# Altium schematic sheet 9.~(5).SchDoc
size 420 x 297 mm
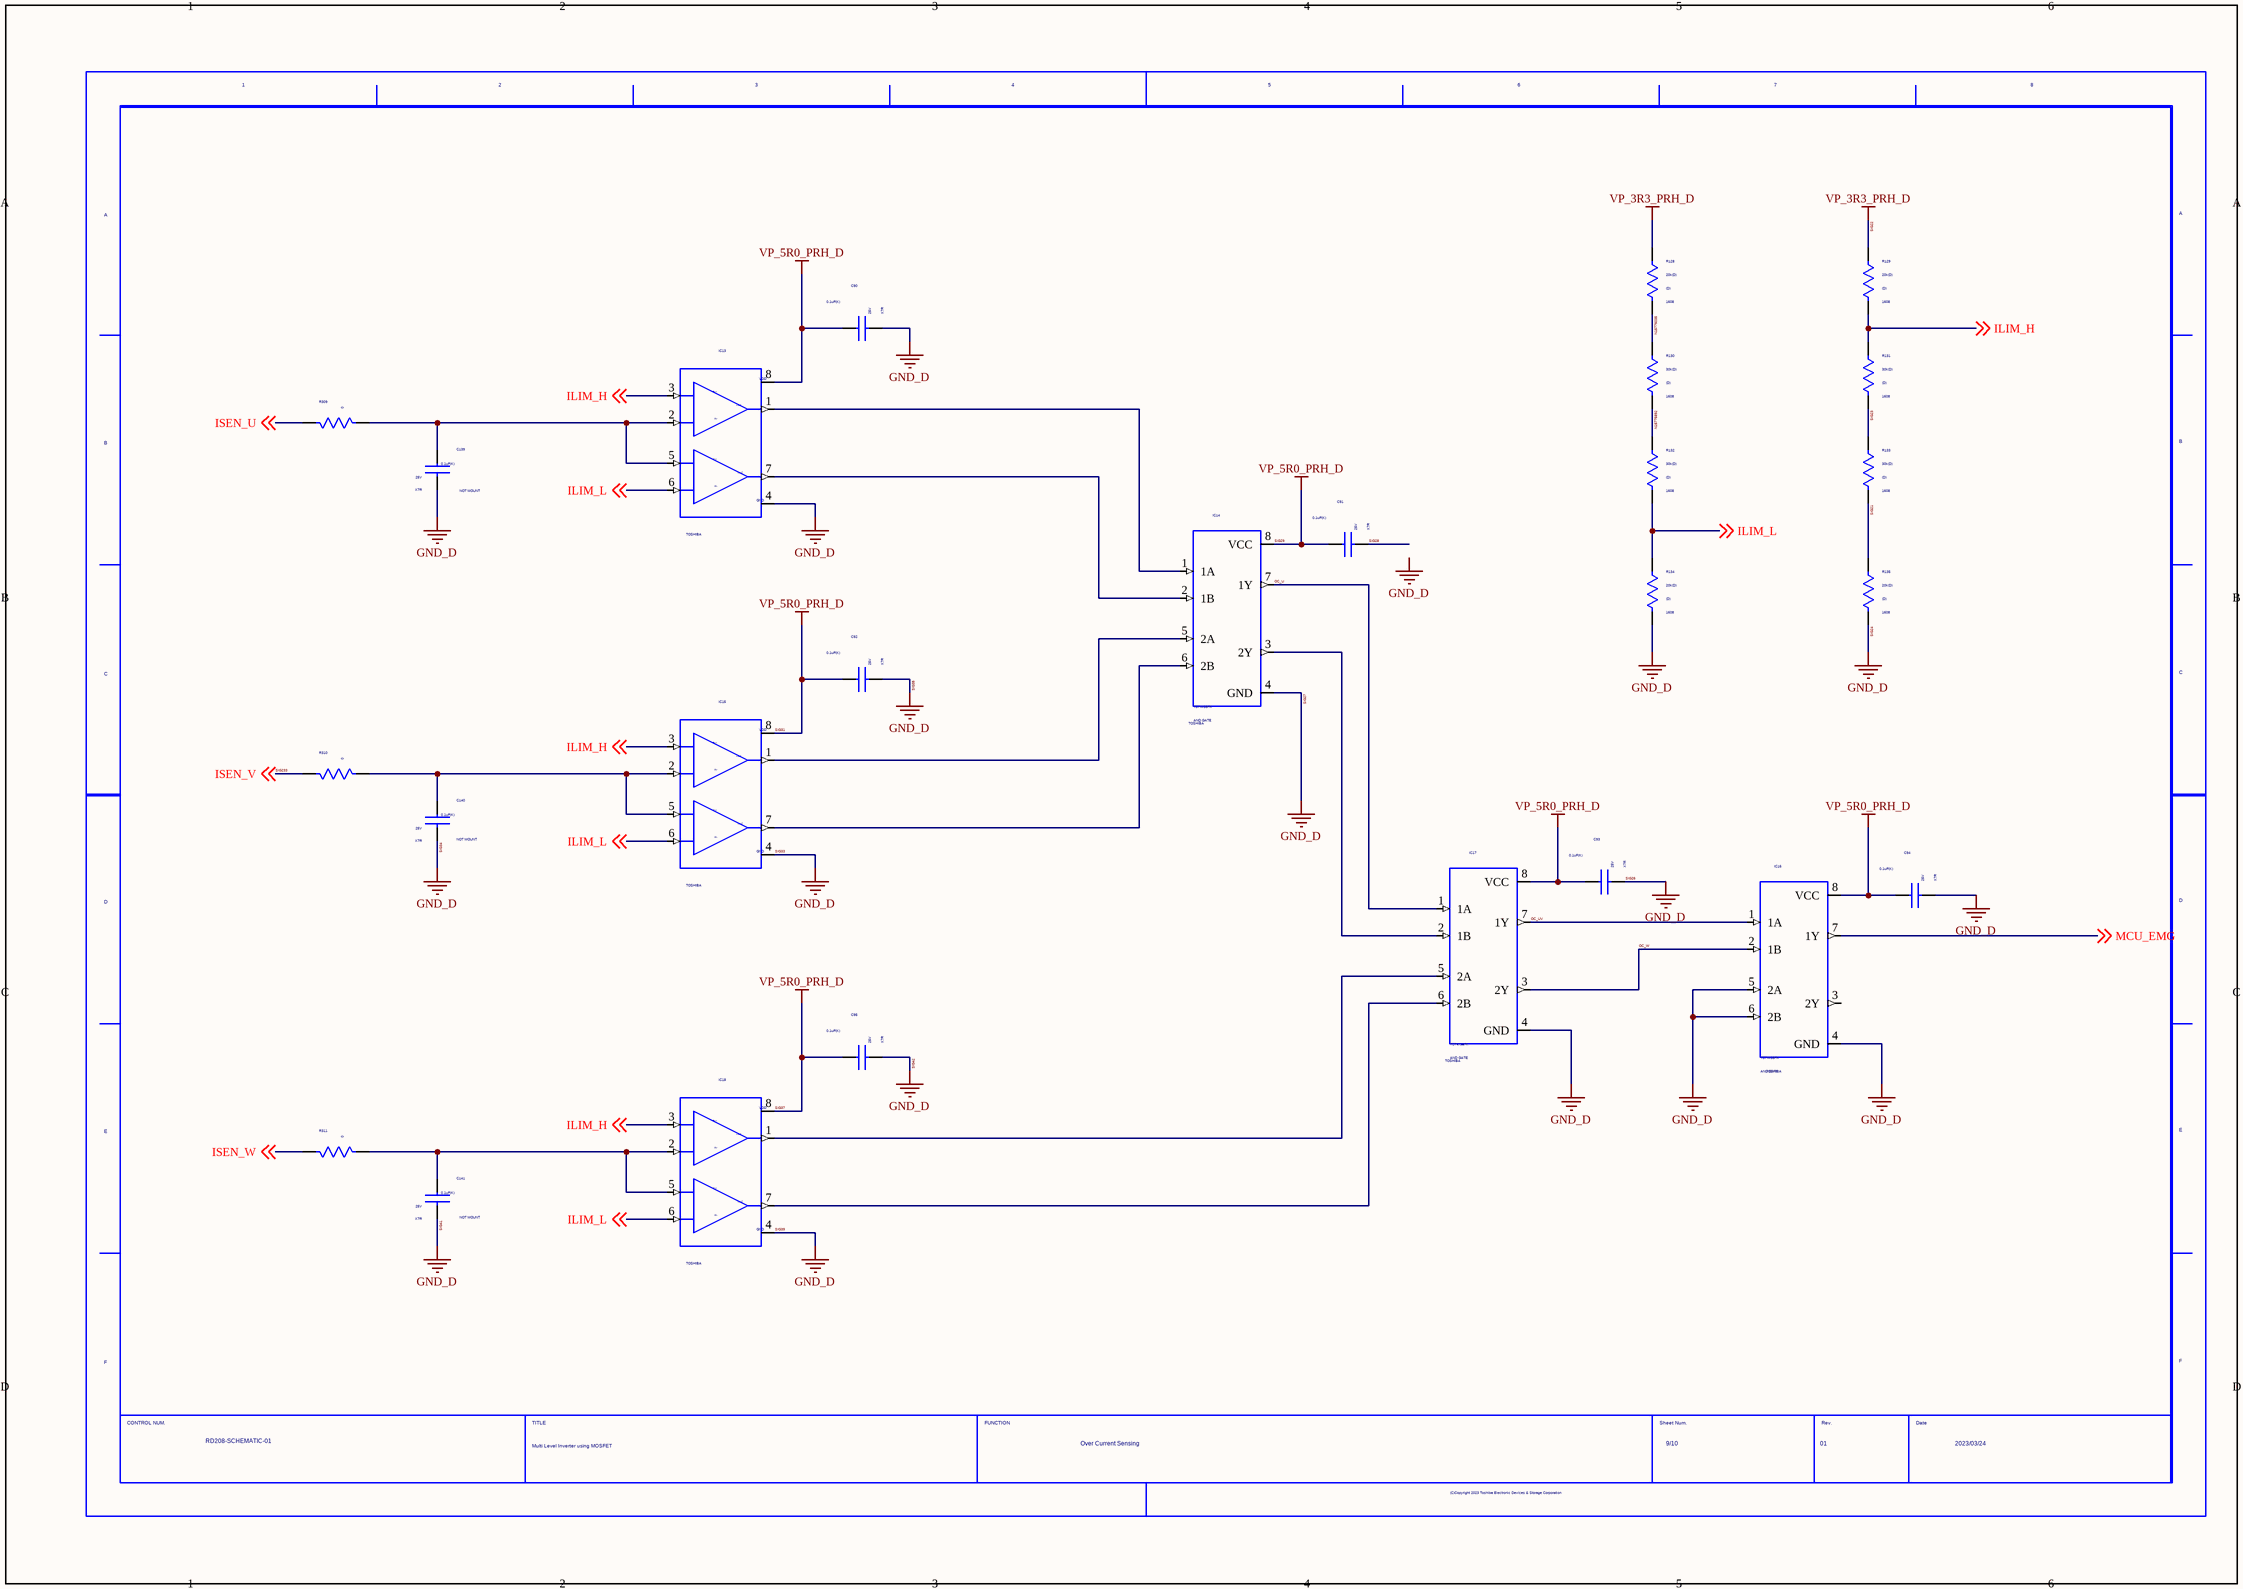
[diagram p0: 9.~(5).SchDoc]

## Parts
C90  VAL2: 25V  VALUE4: X7R  VAL1: 0.1uF(K)  (hidden comment: GRM155R71E104KE14D)
C91  VAL2: 25V  VALUE4: X7R  VAL1: 0.1uF(K)  (hidden comment: GRM155R71E104KE14D)
C92  VAL2: 25V  VALUE4: X7R  VAL1: 0.1uF(K)  (hidden comment: GRM155R71E104KE14D)
C93  VAL2: 25V  VALUE4: X7R  VAL1: 0.1uF(K)  (hidden comment: GRM155R71E104KE14D)
C94  VAL2: 25V  VALUE4: X7R  VAL1: 0.1uF(K)  (hidden comment: GRM155R71E104KE14D)
C95  VAL2: 25V  VALUE4: X7R  VAL1: 0.1uF(K)  (hidden comment: GRM155R71E104KE14D)
C139  VAL2: 25V  VALUE4: X7R  VAL1: 0.1uF(K)  NOTMOUNT: NOT MOUNT  (hidden comment: GRM155R71E104KE14D)
C140  VAL2: 25V  VALUE4: X7R  VAL1: 0.1uF(K)  NOTMOUNT: NOT MOUNT  (hidden comment: GRM155R71E104KE14D)
C141  VAL2: 25V  VALUE4: X7R  VAL1: 0.1uF(K)  NOTMOUNT: NOT MOUNT  (hidden comment: GRM155R71E104KE14D)
IC13  USERCOMPTEXT3: TOSHIBA  (hidden comment: TC75W57FK_TE85L_F_)
IC14  VAL2: AND GATE  USERCOMPTEXT3: TOSHIBA  (hidden comment: TC7W08FK)
IC15  USERCOMPTEXT3: TOSHIBA  (hidden comment: TC75W57FK_TE85L_F_)
IC16  VAL2: AND GATE  USERCOMPTEXT3: TOSHIBA  (hidden comment: TC7W08FK)
IC17  VAL2: AND GATE  USERCOMPTEXT3: TOSHIBA  (hidden comment: TC7W08FK)
IC18  USERCOMPTEXT3: TOSHIBA  (hidden comment: TC75W57FK_TE85L_F_)
R128  SIZECODESMD: 1608  VALUE4: (D)  VAL1: 20k(D)  (hidden comment: ERJ3RBD2002V)
R129  SIZECODESMD: 1608  VALUE4: (D)  VAL1: 20k(D)  (hidden comment: ERJ3RBD2002V)
R130  SIZECODESMD: 1608  VALUE4: (D)  VAL1: 30k(D)  (hidden comment: ERJ3RBD3002V)
R131  SIZECODESMD: 1608  VALUE4: (D)  VAL1: 30k(D)  (hidden comment: ERJ3RBD3002V)
R132  SIZECODESMD: 1608  VALUE4: (D)  VAL1: 30k(D)  (hidden comment: ERJ3RBD3002V)
R133  SIZECODESMD: 1608  VALUE4: (D)  VAL1: 30k(D)  (hidden comment: ERJ3RBD3002V)
R134  SIZECODESMD: 1608  VALUE4: (D)  VAL1: 20k(D)  (hidden comment: ERJ3RBD2002V)
R135  SIZECODESMD: 1608  VALUE4: (D)  VAL1: 20k(D)  (hidden comment: ERJ3RBD2002V)
R309  VAL1: 0  (hidden comment: ERJ2GE0R00X)
R310  VAL1: 0  (hidden comment: ERJ2GE0R00X)
R311  VAL1: 0  (hidden comment: ERJ2GE0R00X)
U?  DATE: 2023/03/24  TITLE: Multi Level Inverter using MOSFET  REVISION: 01  SHEETNUMBER: 9/10  FUNCTION: Over Current Sensing  DRAWINGNUMBER: RD208-SCHEMATIC-01  (hidden comment: WAKU_DEF100)

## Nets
SIG22: R128.1 R129.1  [also labelled VP_3R3_PRH_D]
SIG24: C90.2 C92.2 C93.2 C94.2 C95.2 C139.2 C140.2 C141.2 IC13.4(VSS) IC14.4(GND) IC15.4(VSS) IC16.4(GND) IC16.5(2A) IC16.6(2B) IC17.4(GND) IC18.4(VSS) R134.2 R135.2  [also labelled GND_D, SIG26, SIG27, SIG33, SIG34, SIG35, SIG39, SIG41, SIG42]
SIG29: C90.1 C91.1 C92.1 C93.1 C94.1 C95.1 IC13.8(VDD) IC14.8(VCC) IC15.8(VDD) IC16.8(VCC) IC17.8(VCC) IC18.8(VDD)  [also labelled SIG31, SIG37, VP_5R0_PRH_D]
ILIM_H: IC13.3(INA+) IC15.3(INA+) IC18.3(INA+) R129.2 R131.1 ; off-sheet ILIM_H
ILIM_L: IC13.6(INB-) IC15.6(INB-) IC18.6(INB-) R132.2 R134.1 ; off-sheet ILIM_L
ISEN_U: R309.2 ; off-sheet ISEN_U
ISEN_U_FLT: C139.1 IC13.2(INA-) IC13.5(INB+) R309.1
ISEN_V_FLT: C140.1 IC15.2(INA-) IC15.5(INB+) R310.1
ISEN_W: R311.2 ; off-sheet ISEN_W
ISEN_W_FLT: C141.1 IC18.2(INA-) IC18.5(INB+) R311.1
MCU_EMG: IC16.7(1Y) ; off-sheet MCU_EMG
N15775892: R130.2 R132.1
N15776035: R128.2 R130.1
OC_U: IC14.7(1Y) IC17.1(1A)
OC_U_N: IC13.7(OUTB) IC14.2(1B)
OC_U_P: IC13.1(OUTA) IC14.1(1A)
OC_UV: IC16.1(1A) IC17.7(1Y)
OC_V: IC14.3(2Y) IC17.2(1B)
OC_V_N: IC14.6(2B) IC15.7(OUTB)
OC_V_P: IC14.5(2A) IC15.1(OUTA)
OC_W: IC16.2(1B) IC17.3(2Y)
OC_W_N: IC17.6(2B) IC18.7(OUTB)
OC_W_P: IC17.5(2A) IC18.1(OUTA)
SIG21: R133.2 R135.1
SIG23: R131.2 R133.1
SIG28: C91.2
SIG233: R310.2 ; off-sheet ISEN_V  [also labelled ISEN_V]

Not connected (* = marked no-connect by the designer): IC16 3(2Y)

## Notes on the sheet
- Labels drawn without touching a wire or pin: GND_D

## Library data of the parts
C90-C95 = GRM155R71E104KE14D: MANUFACTURER: MURATA; ITEM: CAP Ceramic; SIZECODESMD: 1005; TIME: 08:44:45; UPDATEUSER: t5459927; SAVECOUNT: 1; OriginalSymbolOrigin: (0,0); INSTANCENAME: INS15829710
C139-C141 = GRM155R71E104KE14D: MANUFACTURER: MURATA; ITEM: CAP Ceramic; SIZECODESMD: 1005; TIME: 08:44:45; UPDATEUSER: t5459927; SAVECOUNT: 1; OriginalSymbolOrigin: (0,0); INSTANCENAME: INS17203421
IC13 IC15 IC18 = TC75W57FK_TE85L_F_: ITEM: IC Comparator; VAL2: COMPARATOR; VAL1: TC75W57FK(TE85L,F); TIME: 08:44:45; UPDATEUSER: PS4_common_PC; UPDATETIME: 11:17:59; SAVECOUNT: 2; SAVEAREA0: -66604,-47529,81816,20099; OriginalSymbolOrigin: (0,0)
IC14 IC17 = TC7W08FK: ITEM: IC Logic; TIME: 08:44:45; UPDATEUSER: t5459927; SAVECOUNT: 1; SAVEAREA0: -18404,-33681,30128,1847; OriginalSymbolOrigin: (0,0); INSTANCENAME: INS15825073
IC16 = TC7W08FK: ITEM: IC Logic; TIME: 08:44:45; UPDATEUSER: t5459927; SAVECOUNT: 1; SAVEAREA0: -18404,-33681,30128,1847; OriginalSymbolOrigin: (0,0); INSTANCENAME: INS15824931
R128 R129 = ERJ3RBD2002V: MANUFACTURER: Panasonic; ITEM: Register; VAL2: 100mW; TIME: 08:44:45; UPDATEUSER: t5459927; SAVECOUNT: 1; OriginalSymbolOrigin: (0,0); INSTANCENAME: INS17170385
R130 R131 = ERJ3RBD3002V: MANUFACTURER: Panasonic; ITEM: Register; VAL2: 100mW; TIME: 08:44:45; UPDATEUSER: t5459927; SAVECOUNT: 1; OriginalSymbolOrigin: (0,0); INSTANCENAME: INS17170440
R132 R133 = ERJ3RBD3002V: MANUFACTURER: Panasonic; ITEM: Register; VAL2: 100mW; TIME: 08:44:45; UPDATEUSER: t5459927; SAVECOUNT: 1; OriginalSymbolOrigin: (0,0); INSTANCENAME: INS17170452
R134 R135 = ERJ3RBD2002V: MANUFACTURER: Panasonic; ITEM: Register; VAL2: 100mW; TIME: 08:44:45; UPDATEUSER: t5459927; SAVECOUNT: 1; OriginalSymbolOrigin: (0,0); INSTANCENAME: INS17170397
R309-R311 = ERJ2GE0R00X: MANUFACTURER: Panasonic; ITEM: Register; VAL2: 1/10W; SIZECODESMD: 1005; TIME: 08:44:45; UPDATEUSER: t5459927; SAVECOUNT: 1; OriginalSymbolOrigin: (0,0); INSTANCENAME: INS17203406
U? = WAKU_DEF100: PLOTTIME: HH:MM; SAVEAREA0: 185750,-43960,448537,75779; TIME: 14:30:25; UPDATEUSER: PS4_common_PC; UPDATETIME: 08:26:12; SAVECOUNT: 8; OriginalSymbolOrigin: (10160,284480)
